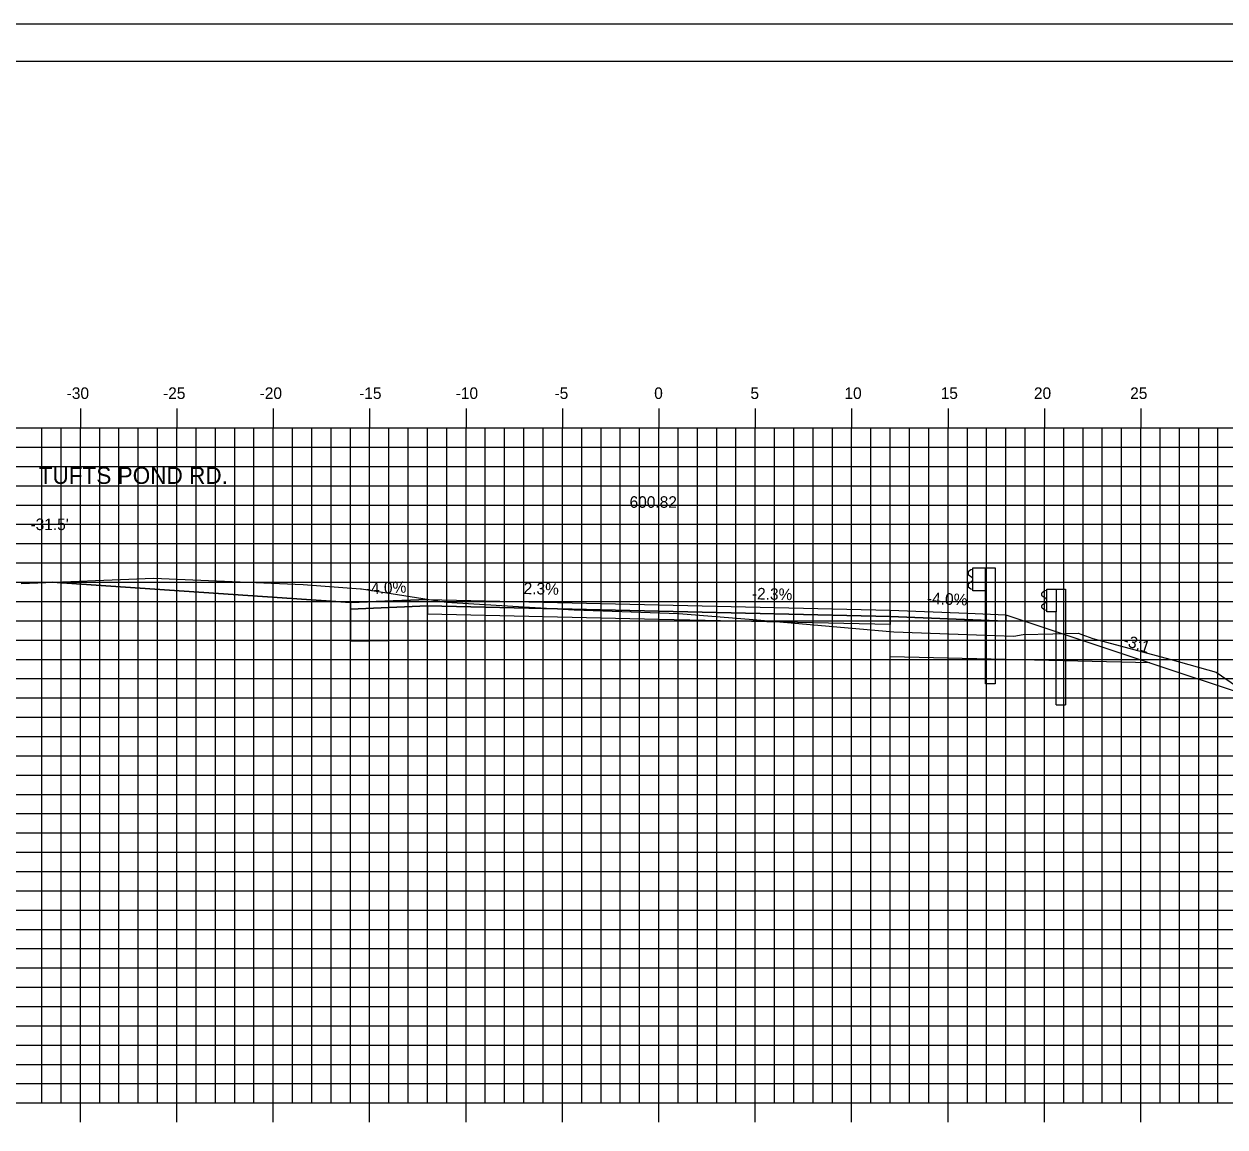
# Model space of a CAD drawing. Extents: x 1073421 to 1073591, y 779716 to 779826.
# Drawn here: x 1073471 to 1073533.3, y 779768.5 to 779825.6 of the extents above; entities that cross this region are included whole.
import ezdxf

# ---------------------------------------------------------------- set-up
doc = ezdxf.new("R2010")
doc.units = 0
for name, color, linetype in [('ANNOTATION', 7, 'Continuous'), ('BORDER', 7, 'Continuous'), ('D_Guardrail_Beam_Rt', 7, 'Continuous'), ('D_Roadway_Centerline', 7, 'Continuous'), ('D_Roadway_Centerline_Text', 7, 'Continuous'), ('D_Roadway_Edge_Pavement', 7, 'Continuous'), ('D_Roadway_Edge_Shoulder', 7, 'Continuous'), ('D_Roadway_Pavement', 7, 'Continuous'), ('D_Roadway_SlopeLines', 7, 'Continuous'), ('D_Roadway_SubGrade', 7, 'Continuous'), ('D_Text_Standard', 7, 'Continuous'), ('H_V ANNOTATION', 7, 'Continuous'), ('M_Guardrail', 7, 'Continuous'), ('MAJOR', 7, 'Continuous'), ('MINOR', 7, 'Continuous'), ('PLOT BOUNDARY', 7, 'Continuous'), ('S_Guardrail_Beam', 7, 'Continuous'), ('S_Roadway_Centerline', 7, 'Continuous')]:
    doc.layers.add(name, color=color, linetype=linetype)

msp = doc.modelspace()

# ---------------------------------------------------------------- linework, layer by layer
at = {"layer": 'BORDER'}
msp.add_lwpolyline([(1073428.959, 779718.706), (1073588.959, 779718.706), (1073588.959, 779823.706), (1073428.959, 779823.706)], close=True, dxfattribs=at)
at = {"layer": 'D_Guardrail_Beam_Rt'}
msp.add_lwpolyline([(1073520.238, 779797.366), (1073520.156, 779797.352), (1073520.139, 779797.345), (1073519.996, 779797.245), (1073519.996, 779797.101), (1073520.191, 779796.965), (1073520.225, 779796.9), (1073520.225, 779796.809), (1073520.191, 779796.745), (1073519.996, 779796.608), (1073519.996, 779796.465), (1073520.139, 779796.365), (1073520.156, 779796.358), (1073520.238, 779796.343)], dxfattribs=at)
for points in [[(1073520.238, 779797.445), (1073520.904, 779797.445), (1073520.904, 779796.264), (1073520.238, 779796.264)], [(1073520.904, 779797.445), (1073521.397, 779797.445), (1073521.397, 779791.441), (1073520.904, 779791.441)]]:
    msp.add_lwpolyline(points, close=True, dxfattribs=at)
at = {"layer": 'D_Roadway_Centerline'}
for points in [[(1073472.486, 779796.706), (1073487.959, 779795.646), (1073491.959, 779795.806), (1073503.959, 779795.53), (1073515.959, 779795.254), (1073519.959, 779795.094), (1073521.959, 779795.014)], [(1073529.418, 779792.528), (1073534.736, 779790.755)]]:
    msp.add_lwpolyline(points, dxfattribs=at)
at = {"layer": 'D_Roadway_Edge_Pavement'}
msp.add_lwpolyline([(1073491.959, 779795.473), (1073491.959, 779795.806), (1073503.959, 779795.53), (1073515.959, 779795.254), (1073515.959, 779794.921), (1073503.959, 779795.197)], close=True, dxfattribs=at)
at = {"layer": 'D_Roadway_Edge_Shoulder'}
msp.add_lwpolyline([(1073491.959, 779795.806), (1073487.959, 779795.646), (1073487.959, 779795.313), (1073491.959, 779795.473)], close=True, dxfattribs=at)
msp.add_lwpolyline([(1073515.959, 779795.254), (1073519.959, 779795.094), (1073521.959, 779795.014), (1073521.959, 779794.681), (1073515.959, 779794.921), (1073515.959, 779795.254)], dxfattribs=at)
at = {"layer": 'D_Roadway_Pavement'}
msp.add_lwpolyline([(1073491.959, 779795.056), (1073491.959, 779795.473), (1073503.959, 779795.197), (1073515.959, 779794.921), (1073515.959, 779794.504), (1073503.959, 779794.78)], close=True, dxfattribs=at)
msp.add_lwpolyline([(1073491.959, 779795.473), (1073491.959, 779795.056)], dxfattribs=at)
at = {"layer": 'D_Roadway_SlopeLines'}
msp.add_lwpolyline([(1073491.959, 779795.806), (1073487.959, 779795.646), (1073472.486, 779796.706)], dxfattribs=at)
at = {"layer": 'D_Roadway_SubGrade'}
for points in [[(1073491.959, 779795.473), (1073487.959, 779795.313), (1073487.959, 779795.646), (1073487.959, 779793.643), (1073491.959, 779793.723)], [(1073515.959, 779792.837), (1073515.959, 779793.421), (1073515.959, 779794.921), (1073515.959, 779794.921), (1073521.959, 779794.681), (1073521.959, 779795.014), (1073529.418, 779792.528)]]:
    msp.add_lwpolyline(points, close=True, dxfattribs=at)
at = {"layer": 'M_Guardrail'}
for p, q in [((1073524.566, 779796.344), (1073525.058, 779796.344)), ((1073525.058, 779796.344), (1073525.058, 779790.344)), ((1073524.566, 779790.344), (1073524.566, 779795.177)), ((1073524.566, 779790.344), (1073525.058, 779790.344))]:
    msp.add_line(p, q, dxfattribs=at)
at = {"layer": 'MAJOR'}
for p, q in [((1073473.959, 779805.708), (1073473.959, 779804.706)), ((1073478.959, 779805.708), (1073478.959, 779804.706)), ((1073483.959, 779805.708), (1073483.959, 779804.706)), ((1073488.959, 779805.708), (1073488.959, 779804.706)), ((1073493.959, 779805.708), (1073493.959, 779804.706)), ((1073498.959, 779805.708), (1073498.959, 779804.706)), ((1073503.959, 779805.708), (1073503.959, 779804.706)), ((1073508.959, 779805.708), (1073508.959, 779804.706)), ((1073513.959, 779805.708), (1073513.959, 779804.706)), ((1073518.959, 779805.708), (1073518.959, 779804.706)), ((1073523.959, 779805.708), (1073523.959, 779804.706)), ((1073528.959, 779805.708), (1073528.959, 779804.706)), ((1073433.959, 779804.706), (1073573.959, 779804.706)), ((1073433.959, 779804.706), (1073573.959, 779804.706)), ((1073473.959, 779769.706), (1073473.959, 779804.706)), ((1073478.959, 779769.706), (1073478.959, 779804.706)), ((1073483.959, 779769.706), (1073483.959, 779804.706)), ((1073488.959, 779769.706), (1073488.959, 779804.706)), ((1073493.959, 779769.706), (1073493.959, 779804.706)), ((1073498.959, 779769.706), (1073498.959, 779804.706)), ((1073503.959, 779769.706), (1073503.959, 779804.706)), ((1073508.959, 779769.706), (1073508.959, 779804.706)), ((1073513.959, 779769.706), (1073513.959, 779804.706)), ((1073518.959, 779769.706), (1073518.959, 779804.706)), ((1073523.959, 779769.706), (1073523.959, 779804.706)), ((1073528.959, 779769.706), (1073528.959, 779804.706)), ((1073433.959, 779799.706), (1073573.959, 779799.706)), ((1073433.959, 779794.706), (1073573.959, 779794.706)), ((1073433.959, 779789.706), (1073573.959, 779789.706)), ((1073433.959, 779784.706), (1073573.959, 779784.706)), ((1073433.959, 779779.706), (1073573.959, 779779.706)), ((1073433.959, 779774.706), (1073573.959, 779774.706)), ((1073433.959, 779769.706), (1073573.959, 779769.706)), ((1073433.959, 779769.706), (1073573.959, 779769.706)), ((1073473.959, 779768.704), (1073473.959, 779769.706)), ((1073478.959, 779768.704), (1073478.959, 779769.706)), ((1073483.959, 779768.704), (1073483.959, 779769.706)), ((1073488.959, 779768.704), (1073488.959, 779769.706)), ((1073493.959, 779768.704), (1073493.959, 779769.706)), ((1073498.959, 779768.704), (1073498.959, 779769.706)), ((1073503.959, 779768.704), (1073503.959, 779769.706)), ((1073508.959, 779768.704), (1073508.959, 779769.706)), ((1073513.959, 779768.704), (1073513.959, 779769.706)), ((1073518.959, 779768.704), (1073518.959, 779769.706)), ((1073523.959, 779768.704), (1073523.959, 779769.706)), ((1073528.959, 779768.704), (1073528.959, 779769.706))]:
    msp.add_line(p, q, dxfattribs=at)
at = {"layer": 'MINOR'}
for p, q in [((1073471.959, 779769.706), (1073471.959, 779804.706)), ((1073472.959, 779769.706), (1073472.959, 779804.706)), ((1073474.959, 779769.706), (1073474.959, 779804.706)), ((1073475.959, 779769.706), (1073475.959, 779804.706)), ((1073476.959, 779769.706), (1073476.959, 779804.706)), ((1073477.959, 779769.706), (1073477.959, 779804.706)), ((1073479.959, 779769.706), (1073479.959, 779804.706)), ((1073480.959, 779769.706), (1073480.959, 779804.706)), ((1073481.959, 779769.706), (1073481.959, 779804.706)), ((1073482.959, 779769.706), (1073482.959, 779804.706)), ((1073484.959, 779769.706), (1073484.959, 779804.706)), ((1073485.959, 779769.706), (1073485.959, 779804.706)), ((1073486.959, 779769.706), (1073486.959, 779804.706)), ((1073487.959, 779769.706), (1073487.959, 779804.706)), ((1073489.959, 779769.706), (1073489.959, 779804.706)), ((1073490.959, 779769.706), (1073490.959, 779804.706)), ((1073491.959, 779769.706), (1073491.959, 779804.706)), ((1073492.959, 779769.706), (1073492.959, 779804.706)), ((1073494.959, 779769.706), (1073494.959, 779804.706)), ((1073495.959, 779769.706), (1073495.959, 779804.706)), ((1073496.959, 779769.706), (1073496.959, 779804.706)), ((1073497.959, 779769.706), (1073497.959, 779804.706)), ((1073499.959, 779769.706), (1073499.959, 779804.706)), ((1073500.959, 779769.706), (1073500.959, 779804.706)), ((1073501.959, 779769.706), (1073501.959, 779804.706)), ((1073502.959, 779769.706), (1073502.959, 779804.706)), ((1073504.959, 779769.706), (1073504.959, 779804.706)), ((1073505.959, 779769.706), (1073505.959, 779804.706)), ((1073506.959, 779769.706), (1073506.959, 779804.706)), ((1073507.959, 779769.706), (1073507.959, 779804.706)), ((1073509.959, 779769.706), (1073509.959, 779804.706)), ((1073510.959, 779769.706), (1073510.959, 779804.706)), ((1073511.959, 779769.706), (1073511.959, 779804.706)), ((1073512.959, 779769.706), (1073512.959, 779804.706)), ((1073514.959, 779769.706), (1073514.959, 779804.706)), ((1073515.959, 779769.706), (1073515.959, 779804.706)), ((1073516.959, 779769.706), (1073516.959, 779804.706)), ((1073517.959, 779769.706), (1073517.959, 779804.706)), ((1073519.959, 779769.706), (1073519.959, 779804.706)), ((1073520.959, 779769.706), (1073520.959, 779804.706)), ((1073521.959, 779769.706), (1073521.959, 779804.706)), ((1073522.959, 779769.706), (1073522.959, 779804.706)), ((1073524.959, 779769.706), (1073524.959, 779804.706)), ((1073525.959, 779769.706), (1073525.959, 779804.706)), ((1073526.959, 779769.706), (1073526.959, 779804.706)), ((1073527.959, 779769.706), (1073527.959, 779804.706)), ((1073529.959, 779769.706), (1073529.959, 779804.706)), ((1073530.959, 779769.706), (1073530.959, 779804.706)), ((1073531.959, 779769.706), (1073531.959, 779804.706)), ((1073532.959, 779769.706), (1073532.959, 779804.706)), ((1073433.959, 779803.706), (1073573.959, 779803.706)), ((1073433.959, 779802.706), (1073573.959, 779802.706)), ((1073433.959, 779801.706), (1073573.959, 779801.706)), ((1073433.959, 779800.706), (1073573.959, 779800.706)), ((1073433.959, 779798.706), (1073573.959, 779798.706)), ((1073433.959, 779797.706), (1073573.959, 779797.706)), ((1073433.959, 779796.706), (1073573.959, 779796.706)), ((1073433.959, 779795.706), (1073573.959, 779795.706)), ((1073433.959, 779793.706), (1073573.959, 779793.706)), ((1073433.959, 779792.706), (1073573.959, 779792.706)), ((1073433.959, 779791.706), (1073573.959, 779791.706)), ((1073433.959, 779790.706), (1073573.959, 779790.706)), ((1073433.959, 779788.706), (1073573.959, 779788.706)), ((1073433.959, 779787.706), (1073573.959, 779787.706)), ((1073433.959, 779786.706), (1073573.959, 779786.706)), ((1073433.959, 779785.706), (1073573.959, 779785.706)), ((1073433.959, 779783.706), (1073573.959, 779783.706)), ((1073433.959, 779782.706), (1073573.959, 779782.706)), ((1073433.959, 779781.706), (1073573.959, 779781.706)), ((1073433.959, 779780.706), (1073573.959, 779780.706)), ((1073433.959, 779778.706), (1073573.959, 779778.706)), ((1073433.959, 779777.706), (1073573.959, 779777.706)), ((1073433.959, 779776.706), (1073573.959, 779776.706)), ((1073433.959, 779775.706), (1073573.959, 779775.706)), ((1073433.959, 779773.706), (1073573.959, 779773.706)), ((1073433.959, 779772.706), (1073573.959, 779772.706)), ((1073433.959, 779771.706), (1073573.959, 779771.706)), ((1073433.959, 779770.706), (1073573.959, 779770.706))]:
    msp.add_line(p, q, dxfattribs=at)
at = {"layer": 'PLOT BOUNDARY'}
msp.add_lwpolyline([(1073420.866, 779715.646), (1073590.866, 779715.646), (1073590.866, 779825.646), (1073420.866, 779825.646)], close=True, dxfattribs=at)
at = {"layer": 'S_Guardrail_Beam'}
for p, q in [((1073523.978, 779796.25), (1073523.834, 779796.15)), ((1073523.834, 779796.007), (1073524.03, 779795.871)), ((1073524.077, 779796.271), (1073523.994, 779796.257)), ((1073524.077, 779796.344), (1073524.566, 779796.344)), ((1073524.077, 779795.177), (1073524.077, 779796.344)), ((1073524.566, 779796.344), (1073524.566, 779795.177)), ((1073524.03, 779795.651), (1073523.834, 779795.515)), ((1073523.834, 779795.371), (1073523.978, 779795.271)), ((1073524.063, 779795.806), (1073524.063, 779795.715)), ((1073523.994, 779795.265), (1073524.077, 779795.25)), ((1073524.566, 779795.177), (1073524.077, 779795.177))]:
    msp.add_line(p, q, dxfattribs=at)
for centre, major_axis, start_param, end_param in [((1073523.885, 779796.078), (-0.0877, 0), 5.323254, 7.243116), ((1073524.002, 779796.216), (-0.0417, 0), 4.886922, 5.323254), ((1073523.885, 779795.443), (-0.0877, 0), 5.323254, 7.243116), ((1073523.984, 779795.806), (0.0789, 0), 0, 0.959931), ((1073523.984, 779795.715), (0.0789, 0), 5.323254, 6.283185), ((1073524.002, 779795.305), (-0.0417, 0), 0.959931, 1.396263)]:
    msp.add_ellipse(centre, major_axis=major_axis, ratio=0.995501, start_param=start_param, end_param=end_param, dxfattribs=at)
at = {"layer": 'S_Roadway_Centerline'}
msp.add_lwpolyline([(1073470.883, 779796.644), (1073477.743, 779796.908), (1073485.515, 779796.59), (1073488.484, 779796.364), (1073488.534, 779796.354), (1073492.936, 779795.663), (1073499.563, 779795.269), (1073505, 779795.077), (1073508.854, 779794.772), (1073516.143, 779794.133), (1073521.378, 779793.945), (1073522.371, 779793.911), (1073522.851, 779793.996), (1073524.387, 779794.021), (1073525.71, 779794.069), (1073526.474, 779793.782), (1073530.465, 779792.713), (1073532.866, 779792.044), (1073543.324, 779784.835)], dxfattribs=at)

# ---------------------------------------------------------------- texts
at = {"layer": 'ANNOTATION'}
msp.add_text('TUFTS POND RD.', height=0.875, dxfattribs=at).set_placement((1073471.795, 779801.803))
for s, rotation, p in [('-4.0%', 2.29061, (1073488.775, 779796.079)), ('2.3%', 358.68243, (1073496.939, 779796.092)), ('-2.3%', 358.68243, (1073508.779, 779795.819)), ('-4.0%', 357.70939, (1073517.855, 779795.579)), ('-3:1', 341.56505, (1073527.997, 779793.455))]:
    msp.add_text(s, height=0.6, rotation=rotation, dxfattribs=at).set_placement(p)
at = {"layer": 'D_Roadway_Centerline_Text'}
msp.add_text('600.82', height=0.6, dxfattribs=at).set_placement((1073502.442, 779800.562))
at = {"layer": 'D_Text_Standard'}
msp.add_text("-31.5'", height=0.6, dxfattribs=at).set_placement((1073471.37, 779799.406))
at = {"layer": 'H_V ANNOTATION'}
for s, p in [('-30', (1073473.247, 779806.206)), ('-25', (1073478.245, 779806.206)), ('-20', (1073483.253, 779806.206)), ('-15', (1073488.416, 779806.206)), ('-10', (1073493.424, 779806.206)), ('-5', (1073498.55, 779806.206)), ('0', (1073503.718, 779806.206)), ('5', (1073508.71, 779806.206)), ('10', (1073513.585, 779806.206)), ('15', (1073518.577, 779806.206)), ('20', (1073523.413, 779806.206)), ('25', (1073528.405, 779806.206))]:
    msp.add_text(s, height=0.6, dxfattribs=at).set_placement(p)

doc.saveas('drawing.dxf')
